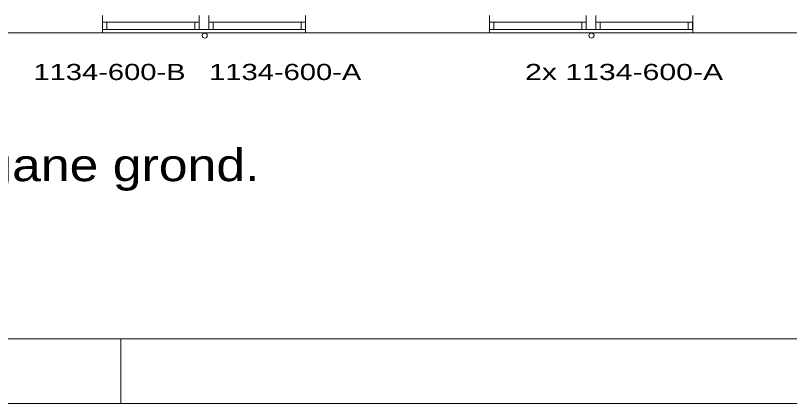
# Model space of a CAD drawing. Extents: x 295824 to 414724, y 24924 to 109024.
# Drawn here: x 308090 to 320090, y 24924 to 30932 of the extents above; entities that cross this region are included whole.
import ezdxf

# ---------------------------------------------------------------- set-up
doc = ezdxf.new("R2010")
doc.units = 0
doc.header["$LTSCALE"] = 100
for name, color, linetype, lineweight in [('1', 7, 'Continuous', 13), ('16', 7, 'Continuous', 13), ('61', 7, 'Continuous', 13)]:
    doc.layers.add(name, color=color, linetype=linetype, lineweight=lineweight)

msp = doc.modelspace()

# ---------------------------------------------------------------- linework, layer by layer
at = {"layer": '1'}
for p, q in [((309723.6, 24923.8), (309723.6, 25923.8)), ((304995.6, 24923.8), (414723.6, 24923.8))]:
    msp.add_line(p, q, dxfattribs=at)
msp.add_lwpolyline([(304995.6, 25923.8), (413723.6, 25923.8), (413723.6, 108023.8), (304995.6, 108023.8)], dxfattribs=at)
at = {"layer": '61'}
for p, q in [((309438.8, 30932), (309438.8, 30662)), ((310938.8, 30932), (310938.8, 30717.3)), ((311087.8, 30932), (311087.8, 30717.3)), ((312587.8, 30932), (312587.8, 30662)), ((315439.4, 30932), (315439.4, 30662)), ((316939.4, 30932), (316939.4, 30717.3)), ((317088.4, 30932), (317088.4, 30717.3)), ((318588.4, 30932), (318588.4, 30662)), ((309439, 30830.3), (309439, 30717.3)), ((310938, 30831.3), (309439.9, 30831.3)), ((309506, 30830.8), (309506, 30717.9)), ((310871, 30831.3), (310871, 30717.9)), ((310938, 30831.3), (310938, 30717.3)), ((311088, 30830.3), (311088, 30717.3)), ((312587, 30831.3), (311088.9, 30831.3)), ((311155, 30830.8), (311155, 30717.3)), ((312520, 30831.3), (312520, 30717.9)), ((312587, 30831.3), (312587, 30717.3)), ((315439.5, 30830.3), (315439.5, 30717.3)), ((316938.6, 30831.3), (315440.5, 30831.3)), ((315506.5, 30830.8), (315506.5, 30717.9)), ((316871.6, 30831.3), (316871.6, 30717.9)), ((316938.6, 30831.3), (316938.6, 30717.3)), ((317088.5, 30830.3), (317088.5, 30717.3)), ((318587.6, 30831.3), (317089.5, 30831.3)), ((317155.5, 30830.8), (317155.5, 30717.3)), ((318520.6, 30831.3), (318520.6, 30717.9)), ((318587.6, 30831.3), (318587.6, 30717.3)), ((326190, 30663.6), (307806, 30663.6)), ((311155, 30717.3), (309439, 30717.3)), ((312587, 30717.3), (311088, 30717.3)), ((317155.5, 30717.3), (315439.5, 30717.3)), ((318587.6, 30717.3), (317088.5, 30717.3))]:
    msp.add_line(p, q, dxfattribs=at)
for centre in [(311024, 30620.7), (317018.9, 30620.7)]:
    msp.add_circle(centre, 40, dxfattribs=at)

# ---------------------------------------------------------------- texts
at = {"layer": '16'}
for s, width, p in [('1134-600-B', 1.35, (308368.5, 29932.7)), ('1134-600-A', 1.35, (311092.7, 29932.7)), ('2x 1134-600-A', 1.4, (315990.2, 29932.7))]:
    msp.add_text(s, height=250, dxfattribs=dict(at, width=width)).set_placement(p)
at = {"layer": '61', "width": 1.2}
msp.add_text('Plattegrond begane grond.', height=500, dxfattribs=at).set_placement((302371.3, 28366.7))

doc.saveas('drawing.dxf')
